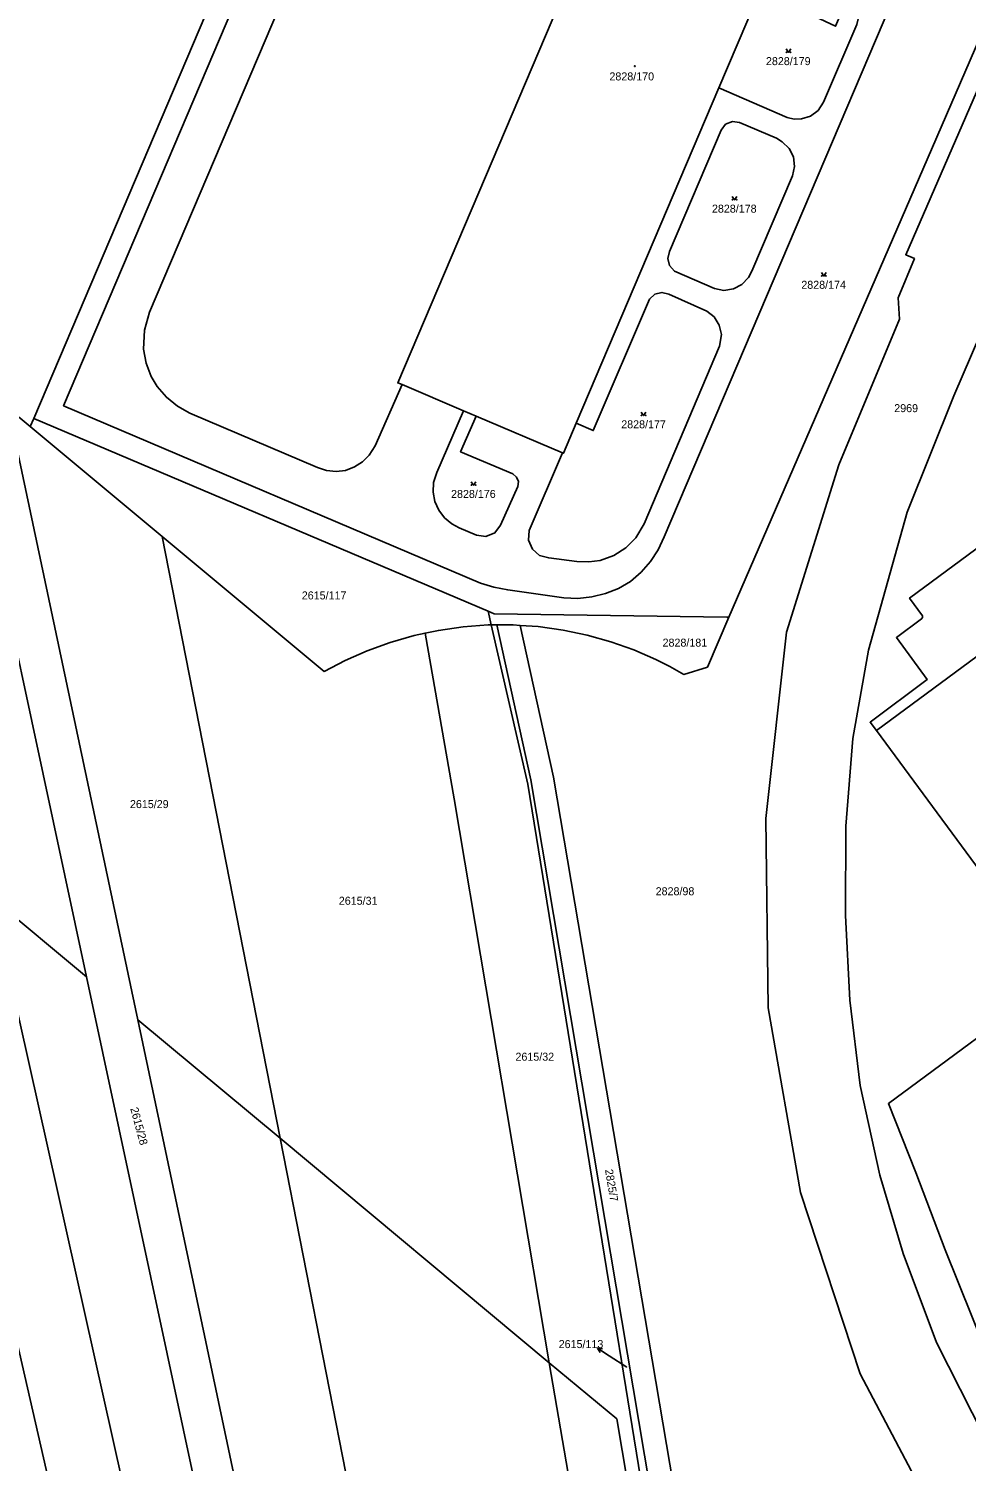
# Model space of a CAD drawing. Extents: x -596024 to -594475, y -1163820 to -1161957.
# Drawn here: x -595048.9 to -594849.7, y -1162870.2 to -1162565.8 of the extents above; entities that cross this region are included whole.
import ezdxf

# ---------------------------------------------------------------- set-up
doc = ezdxf.new("R2010")
doc.units = 0
for name, color, linetype in [('Level 1', 7, 'Continuous'), ('Level 4', 7, 'Continuous'), ('Level 5', 7, 'Continuous'), ('Level 57', 7, 'Continuous'), ('Level 60', 7, 'Continuous')]:
    doc.layers.add(name, color=color, linetype=linetype)

msp = doc.modelspace()

# ---------------------------------------------------------------- linework, layer by layer
at = {"layer": 'Level 1'}
for points in [[(-594848.96, -1162542.18), (-594851.99, -1162542.41), (-594854.86, -1162543.36), (-594857.46, -1162544.9), (-594859.6, -1162547.02), (-594861.11, -1162549.64), (-594913.9, -1162673.81), (-594915.2, -1162676.52), (-594916.84, -1162679.01), (-594918.78, -1162681.28), (-594921.04, -1162683.24), (-594923.61, -1162684.75), (-594926.38, -1162685.85), (-594929.28, -1162686.54), (-594932.25, -1162686.85), (-594935.26, -1162686.74), (-594947.14, -1162685.06), (-594950.08, -1162684.51), (-594952.91, -1162683.6), (-595041.5, -1162645.93), (-594995.82, -1162538.47), (-594955.82, -1162444.57)], [(-594957.28, -1162470.91), (-595023.23, -1162626.01), (-595024.33, -1162629.88), (-595024.5, -1162633.88), (-595023.95, -1162636.85), (-595022.88, -1162639.68), (-595021.58, -1162641.83), (-595019.66, -1162644.12), (-595017.3, -1162646.01), (-595014.7, -1162647.48), (-594987.54, -1162659.08), (-594985.61, -1162659.68), (-594983.61, -1162659.9), (-594981.61, -1162659.67), (-594979.66, -1162658.91), (-594978, -1162657.87), (-594976.57, -1162656.43), (-594975.27, -1162654.44), (-594969.59, -1162641.44)], [(-594969.59, -1162641.44), (-594970.49, -1162641.06), (-594909.2, -1162496.84), (-594908.33, -1162497.21)], [(-595047.84, -1162648.63), (-594999.13, -1162534.19), (-594992.61, -1162518.86)], [(-594822.04, -1162520.38), (-594862.6, -1162613.86), (-594860.74, -1162614.64), (-594864.21, -1162622.98), (-594863.9, -1162627.5), (-594876.82, -1162658.46), (-594887.95, -1162694.06), (-594892.35, -1162733.63), (-594891.85, -1162773.83), (-594884.93, -1162813.13), (-594872.3, -1162851.66), (-594853.89, -1162886.54)], [(-594902.28, -1162578.39), (-594888.34, -1162545.59)], [(-594902.28, -1162578.39), (-594887.77, -1162584.67), (-594886.29, -1162585.01), (-594884.76, -1162584.97), (-594882.81, -1162584.38), (-594881.18, -1162583.16), (-594880.06, -1162581.45), (-594873.01, -1162564.91), (-594872.66, -1162563.41), (-594872.95, -1162561.89), (-594873.75, -1162560.57), (-594875.09, -1162559.62), (-594877.51, -1162565.3), (-594887.39, -1162560.64), (-594885.98, -1162557.21), (-594887.95, -1162555.38), (-594888.69, -1162554.08), (-594889.18, -1162552.61), (-594889.28, -1162551.1), (-594889.09, -1162549.61), (-594888.75, -1162548.42), (-594887.67, -1162545.92), (-594888.34, -1162545.59)], [(-594900.15, -1162690.86), (-594858.06, -1162593.6), (-594837.7, -1162546.58)], [(-594820.79, -1162570.53), (-594852.35, -1162643.82), (-594862.28, -1162668.54), (-594870.52, -1162697.83), (-594873.81, -1162716.63), (-594875.35, -1162735.24), (-594875.39, -1162754.24), (-594874.5, -1162772.2), (-594872.29, -1162790.37), (-594868.13, -1162809.43), (-594863.17, -1162826.03), (-594856.03, -1162844.95), (-594843.44, -1162869.87), (-594838.3, -1162876.69)], [(-594932.57, -1162649.64), (-594902.28, -1162578.39)], [(-594912.78, -1162613.15), (-594913.15, -1162614.65), (-594912.76, -1162616.16), (-594911.7, -1162617.3), (-594903.22, -1162621.04), (-594901.21, -1162621.41), (-594899.21, -1162621.12), (-594897.39, -1162620.19), (-594895.98, -1162618.71), (-594895.29, -1162617.35), (-594886.67, -1162597.06), (-594886.24, -1162595.06), (-594886.43, -1162593.03), (-594887.34, -1162591.24), (-594888.82, -1162589.82), (-594890.08, -1162589.1), (-594897.89, -1162585.73), (-594899.43, -1162585.54), (-594900.86, -1162586.13), (-594901.81, -1162587.35), (-594912.78, -1162613.15)], [(-594868.84, -1162714.93), (-594870.17, -1162713.18), (-594858.08, -1162704.12), (-594864.59, -1162695.18), (-594859.22, -1162691.23), (-594859.01, -1162690.89), (-594859.07, -1162690.55), (-594861.79, -1162686.8), (-594753.98, -1162607.16), (-594752.15, -1162609.62)], [(-594935.5, -1162655.93), (-594942.58, -1162672.47), (-594942.71, -1162674.52), (-594941.9, -1162676.4), (-594940.39, -1162677.76), (-594938.43, -1162678.27), (-594932.46, -1162679.03), (-594929.93, -1162679.09), (-594927.48, -1162678.8), (-594924.63, -1162677.78), (-594922.09, -1162676.14), (-594919.94, -1162674.02), (-594918.14, -1162671.01), (-594902.13, -1162633.25), (-594901.72, -1162630.81), (-594902.23, -1162628.78), (-594903.3, -1162627.06), (-594904.87, -1162625.8), (-594912.91, -1162622.21), (-594914.4, -1162621.85), (-594915.92, -1162622.22), (-594917.06, -1162623.3), (-594928.97, -1162651.21), (-594932.57, -1162649.64)], [(-594868.84, -1162714.93), (-594742.69, -1162621.79), (-594713.66, -1162661.06), (-594839.86, -1162754.27)], [(-595064.49, -1162637.07), (-595036.64, -1162767.29)], [(-594969.59, -1162641.44), (-594956.56, -1162646.98)], [(-595053.16, -1162646.51), (-595048.56, -1162650.34)], [(-595025.72, -1162776.4), (-595053.16, -1162646.51)], [(-594956.56, -1162646.98), (-594962.21, -1162660.12), (-594962.9, -1162662.24), (-594963.01, -1162664.27), (-594962.63, -1162666.24), (-594961.8, -1162668.09), (-594960.59, -1162669.71), (-594959.05, -1162671.01), (-594957.48, -1162671.87), (-594953.79, -1162673.45), (-594951.78, -1162673.73), (-594949.87, -1162672.96), (-594948.65, -1162671.32), (-594944.98, -1162663.08), (-594944.85, -1162662.02), (-594945.28, -1162661.07), (-594946.08, -1162660.36), (-594957.14, -1162655.71), (-594953.87, -1162648.12)], [(-594956.56, -1162646.98), (-594953.87, -1162648.12)], [(-595048.56, -1162650.34), (-595047.84, -1162648.63)], [(-595048.56, -1162650.34), (-595020.55, -1162673.69)], [(-595047.84, -1162648.63), (-594951.3, -1162689.61)], [(-594953.87, -1162648.12), (-594935.5, -1162655.93)], [(-594935.5, -1162655.93), (-594935.28, -1162656.02), (-594932.57, -1162649.64)], [(-595020.55, -1162673.69), (-594986.14, -1162702.38), (-594981.66, -1162700.04), (-594976.97, -1162697.97), (-594972.09, -1162696.2), (-594967.04, -1162694.75), (-594964.69, -1162694.25)], [(-595020.55, -1162673.69), (-594995.49, -1162801.59)], [(-594951.3, -1162689.61), (-594950.04, -1162690.15), (-594900.58, -1162690.85), (-594900.15, -1162690.86)], [(-594951.3, -1162689.61), (-594950.64, -1162692.51)], [(-594964.69, -1162694.25), (-594961.88, -1162693.65), (-594956.62, -1162692.89), (-594951.3, -1162692.51), (-594950.64, -1162692.51)], [(-594950.64, -1162692.51), (-594949.48, -1162692.51)], [(-594950.64, -1162692.51), (-594942.9, -1162726.35), (-594904.01, -1162965.74), (-594906.27, -1162966.3)], [(-594949.48, -1162692.51), (-594945.97, -1162692.5), (-594944.53, -1162692.6)], [(-594895.5, -1163030.2), (-594896.34, -1162998.11), (-594942.24, -1162725.43), (-594949.48, -1162692.51)], [(-594944.53, -1162692.6), (-594940.65, -1162692.86), (-594935.4, -1162693.58), (-594930.25, -1162694.66), (-594925.22, -1162696.07), (-594920.36, -1162697.8), (-594915.69, -1162699.83), (-594912.69, -1162701.36), (-594909.75, -1162703.02), (-594904.74, -1162701.46), (-594900.15, -1162690.86)], [(-594911.92, -1162875.41), (-594937.42, -1162724.86), (-594944.53, -1162692.6)], [(-594964.69, -1162694.25), (-594958.51, -1162729.47), (-594938.33, -1162849.26)], [(-594839.86, -1162754.27), (-594868.84, -1162714.93)], [(-595076.87, -1162733.76), (-595010.01, -1163025.93)], [(-594995.58, -1163024.52), (-595056.72, -1162750.56)], [(-595056.72, -1162750.56), (-595036.64, -1162767.29)], [(-595036.64, -1162767.29), (-594981.78, -1163023.84)], [(-594830.23, -1162767.57), (-594866.26, -1162794.21), (-594860.48, -1162808.87), (-594854.22, -1162825.29), (-594845.65, -1162846.63), (-594845.2, -1162847.51), (-594844.22, -1162848.89), (-594830.45, -1162867.58), (-594816.13, -1162857.08)], [(-594973.5, -1163023.6), (-595025.72, -1162776.4)], [(-594995.49, -1162801.59), (-595025.72, -1162776.4)], [(-594995.49, -1162801.59), (-594951.53, -1163025.94)], [(-594938.33, -1162849.26), (-594995.49, -1162801.59)], [(-594938.33, -1162849.26), (-594917.9, -1162968.52)], [(-594938.33, -1162849.26), (-594924, -1162861.2), (-594906.27, -1162966.3)]]:
    msp.add_lwpolyline(points, dxfattribs=at)
at = {"layer": 'Level 5'}
for points in [[(-594888, -1162570.1), (-594887.5, -1162570.85), (-594887, -1162570.1)], [(-594899.45, -1162601.45), (-594898.95, -1162602.2), (-594898.45, -1162601.45)], [(-594880.49, -1162617.63), (-594879.99, -1162618.38), (-594879.49, -1162617.63)], [(-594918.78, -1162647.27), (-594918.28, -1162648.02), (-594917.78, -1162647.27)], [(-594954.89, -1162662.07), (-594954.39, -1162662.82), (-594953.89, -1162662.07)]]:
    msp.add_lwpolyline(points, dxfattribs=at)
for centre, radius in [((-594887.95, -1162570.8), 0.05), ((-594887.05, -1162570.8), 0.05), ((-594920.14, -1162573.76), 0.09), ((-594920.14, -1162573.76), 0.0521), ((-594899.4, -1162602.15), 0.05), ((-594898.5, -1162602.15), 0.05), ((-594880.44, -1162618.33), 0.05), ((-594879.54, -1162618.33), 0.05), ((-594918.73, -1162647.97), 0.05), ((-594917.83, -1162647.97), 0.05), ((-594954.84, -1162662.77), 0.05), ((-594953.94, -1162662.77), 0.05)]:
    msp.add_circle(centre, radius, dxfattribs=at)
at = {"layer": 'Level 57'}
for p, q in [((-594925.58, -1162847.81), (-594928.09, -1162846.16)), ((-594921.86, -1162850.25), (-594925.58, -1162847.81))]:
    msp.add_line(p, q, dxfattribs=at)
msp.add_lwpolyline([(-594927.53, -1162847.13), (-594928.09, -1162846.16), (-594926.98, -1162846.29)], dxfattribs=at)
at = {"layer": 'Level 60'}
for points in [[(-595059.52, -1162377.94), (-594996.96, -1162405.12), (-595003.2, -1162423.54), (-595011.25, -1162446.58), (-595019.37, -1162469.64), (-595021.91, -1162477.59), (-595014.66, -1162477.2), (-595009.74, -1162476.96), (-595003.68, -1162483.88), (-594998.47, -1162495.55), (-594992.61, -1162518.86), (-594999.13, -1162534.19), (-595047.84, -1162648.63), (-595048.56, -1162650.34), (-595053.16, -1162646.51)], [(-594853.89, -1162886.54), (-594872.3, -1162851.66), (-594884.93, -1162813.13), (-594891.85, -1162773.83), (-594892.35, -1162733.63), (-594887.95, -1162694.06), (-594876.82, -1162658.46), (-594863.9, -1162627.5), (-594864.21, -1162622.98), (-594860.74, -1162614.64), (-594862.6, -1162613.86), (-594822.04, -1162520.38), (-594817.99, -1162511.04), (-594816.51, -1162511.6), (-594796.75, -1162466.29), (-594771.27, -1162407.45), (-594764.73, -1162395.02)], [(-594837.7, -1162546.58), (-594858.06, -1162593.6), (-594900.15, -1162690.86), (-594900.58, -1162690.85), (-594950.04, -1162690.15), (-594951.3, -1162689.61), (-595047.84, -1162648.63), (-594999.13, -1162534.19), (-594992.61, -1162518.86), (-594952.46, -1162424.45), (-594811.37, -1162485.74)], [(-594848.96, -1162542.18), (-594851.99, -1162542.41), (-594854.86, -1162543.36), (-594857.46, -1162544.9), (-594859.6, -1162547.02), (-594861.11, -1162549.64), (-594913.9, -1162673.81), (-594915.2, -1162676.52), (-594916.84, -1162679.01), (-594918.78, -1162681.28), (-594921.04, -1162683.24), (-594923.61, -1162684.75), (-594926.38, -1162685.85), (-594929.28, -1162686.54), (-594932.25, -1162686.85), (-594935.26, -1162686.74), (-594947.14, -1162685.06), (-594950.08, -1162684.51), (-594952.91, -1162683.6), (-595041.5, -1162645.93), (-594995.82, -1162538.47), (-594955.82, -1162444.57), (-594889.14, -1162472.85), (-594848.66, -1162490.1)], [(-594957.28, -1162470.91), (-595023.23, -1162626.01), (-595024.33, -1162629.88), (-595024.5, -1162633.88), (-595023.95, -1162636.85), (-595022.88, -1162639.68), (-595021.58, -1162641.83), (-595019.66, -1162644.12), (-595017.3, -1162646.01), (-595014.7, -1162647.48), (-594987.54, -1162659.08), (-594985.61, -1162659.68), (-594983.61, -1162659.9), (-594981.61, -1162659.67), (-594979.66, -1162658.91), (-594978, -1162657.87), (-594976.57, -1162656.43), (-594975.27, -1162654.44), (-594969.59, -1162641.44)], [(-594909.2, -1162496.84), (-594970.49, -1162641.06), (-594969.59, -1162641.44), (-594975.27, -1162654.44), (-594976.57, -1162656.43), (-594978, -1162657.87), (-594979.66, -1162658.91), (-594981.61, -1162659.67), (-594983.61, -1162659.9), (-594985.61, -1162659.68), (-594987.54, -1162659.08), (-595014.7, -1162647.48), (-595017.3, -1162646.01), (-595019.66, -1162644.12), (-595021.58, -1162641.83), (-595022.88, -1162639.68), (-595023.95, -1162636.85), (-595024.5, -1162633.88), (-595024.33, -1162629.88), (-595023.23, -1162626.01), (-594957.28, -1162470.91)], [(-594822.04, -1162520.38), (-594862.6, -1162613.86), (-594860.74, -1162614.64), (-594864.21, -1162622.98), (-594863.9, -1162627.5), (-594876.82, -1162658.46), (-594887.95, -1162694.06), (-594892.35, -1162733.63), (-594891.85, -1162773.83), (-594884.93, -1162813.13), (-594872.3, -1162851.66), (-594853.89, -1162886.54)], [(-594995.82, -1162538.47), (-595041.5, -1162645.93), (-594952.91, -1162683.6), (-594950.08, -1162684.51), (-594947.14, -1162685.06), (-594935.26, -1162686.74), (-594932.25, -1162686.85), (-594929.28, -1162686.54), (-594926.38, -1162685.85), (-594923.61, -1162684.75), (-594921.04, -1162683.24), (-594918.78, -1162681.28), (-594916.84, -1162679.01), (-594915.2, -1162676.52), (-594913.9, -1162673.81), (-594861.11, -1162549.64)], [(-594911.92, -1162875.41), (-594937.42, -1162724.86), (-594944.53, -1162692.6), (-594940.65, -1162692.86), (-594935.4, -1162693.58), (-594930.25, -1162694.66), (-594925.22, -1162696.07), (-594920.36, -1162697.8), (-594915.69, -1162699.83), (-594912.69, -1162701.36), (-594909.75, -1162703.02), (-594904.74, -1162701.46), (-594900.15, -1162690.86), (-594858.06, -1162593.6), (-594837.7, -1162546.58)], [(-594969.59, -1162641.44), (-594956.56, -1162646.98), (-594962.21, -1162660.12), (-594962.9, -1162662.24), (-594963.01, -1162664.27), (-594962.63, -1162666.24), (-594961.8, -1162668.09), (-594960.59, -1162669.71), (-594959.05, -1162671.01), (-594957.48, -1162671.87), (-594953.79, -1162673.45), (-594951.78, -1162673.73), (-594949.87, -1162672.96), (-594948.65, -1162671.32), (-594944.98, -1162663.08), (-594944.85, -1162662.02), (-594945.28, -1162661.07), (-594946.08, -1162660.36), (-594957.14, -1162655.71), (-594953.87, -1162648.12), (-594935.5, -1162655.93), (-594942.58, -1162672.47), (-594942.71, -1162674.52), (-594941.9, -1162676.4), (-594940.39, -1162677.76), (-594938.43, -1162678.27), (-594932.46, -1162679.03), (-594929.93, -1162679.09), (-594927.48, -1162678.8), (-594924.63, -1162677.78), (-594922.09, -1162676.14), (-594919.94, -1162674.02), (-594918.14, -1162671.01), (-594902.13, -1162633.25), (-594901.72, -1162630.81), (-594902.23, -1162628.78), (-594903.3, -1162627.06), (-594904.87, -1162625.8), (-594912.91, -1162622.21), (-594914.4, -1162621.85), (-594915.92, -1162622.22), (-594917.06, -1162623.3), (-594928.97, -1162651.21), (-594932.57, -1162649.64), (-594902.28, -1162578.39), (-594887.77, -1162584.67), (-594886.29, -1162585.01), (-594884.76, -1162584.97), (-594882.81, -1162584.38), (-594881.18, -1162583.16), (-594880.06, -1162581.45), (-594873.01, -1162564.91)], [(-594843.44, -1162869.87), (-594856.03, -1162844.95), (-594863.17, -1162826.03), (-594868.13, -1162809.43), (-594872.29, -1162790.37), (-594874.5, -1162772.2), (-594875.39, -1162754.24), (-594875.35, -1162735.24), (-594873.81, -1162716.63), (-594870.52, -1162697.83), (-594862.28, -1162668.54), (-594852.35, -1162643.82), (-594820.79, -1162570.53)], [(-594820.79, -1162570.53), (-594852.35, -1162643.82), (-594862.28, -1162668.54), (-594870.52, -1162697.83), (-594873.81, -1162716.63), (-594875.35, -1162735.24), (-594875.39, -1162754.24), (-594874.5, -1162772.2), (-594872.29, -1162790.37), (-594868.13, -1162809.43), (-594863.17, -1162826.03), (-594856.03, -1162844.95), (-594843.44, -1162869.87)], [(-594753.98, -1162607.16), (-594861.79, -1162686.8), (-594859.07, -1162690.55), (-594859.01, -1162690.89), (-594859.22, -1162691.23), (-594864.59, -1162695.18), (-594858.08, -1162704.12), (-594870.17, -1162713.18), (-594868.84, -1162714.93), (-594839.86, -1162754.27)], [(-594742.69, -1162621.79), (-594868.84, -1162714.93), (-594870.17, -1162713.18), (-594858.08, -1162704.12), (-594864.59, -1162695.18), (-594859.22, -1162691.23), (-594859.01, -1162690.89), (-594859.07, -1162690.55), (-594861.79, -1162686.8), (-594753.98, -1162607.16)], [(-594830.23, -1162767.57), (-594866.26, -1162794.21), (-594860.48, -1162808.87), (-594854.22, -1162825.29), (-594845.65, -1162846.63)]]:
    msp.add_lwpolyline(points, dxfattribs=at)
for points in [[(-594969.59, -1162641.44), (-594970.49, -1162641.06), (-594909.2, -1162496.84), (-594908.33, -1162497.21), (-594886.94, -1162506.33), (-594873.99, -1162511.84), (-594885.09, -1162537.94), (-594888.34, -1162545.59), (-594902.28, -1162578.39), (-594932.57, -1162649.64), (-594935.28, -1162656.02), (-594935.5, -1162655.93), (-594953.87, -1162648.12), (-594956.56, -1162646.98)], [(-594902.28, -1162578.39), (-594888.34, -1162545.59), (-594887.67, -1162545.92), (-594888.75, -1162548.42), (-594889.09, -1162549.61), (-594889.28, -1162551.1), (-594889.18, -1162552.61), (-594888.69, -1162554.08), (-594887.95, -1162555.38), (-594885.98, -1162557.21), (-594887.39, -1162560.64), (-594877.51, -1162565.3), (-594875.09, -1162559.62), (-594873.75, -1162560.57), (-594872.95, -1162561.89), (-594872.66, -1162563.41), (-594873.01, -1162564.91), (-594880.06, -1162581.45), (-594881.18, -1162583.16), (-594882.81, -1162584.38), (-594884.76, -1162584.97), (-594886.29, -1162585.01), (-594887.77, -1162584.67)], [(-594912.78, -1162613.15), (-594913.15, -1162614.65), (-594912.76, -1162616.16), (-594911.7, -1162617.3), (-594903.22, -1162621.04), (-594901.21, -1162621.41), (-594899.21, -1162621.12), (-594897.39, -1162620.19), (-594895.98, -1162618.71), (-594895.29, -1162617.35), (-594886.67, -1162597.06), (-594886.24, -1162595.06), (-594886.43, -1162593.03), (-594887.34, -1162591.24), (-594888.82, -1162589.82), (-594890.08, -1162589.1), (-594897.89, -1162585.73), (-594899.43, -1162585.54), (-594900.86, -1162586.13), (-594901.81, -1162587.35)], [(-594913.15, -1162614.65), (-594912.78, -1162613.15), (-594901.81, -1162587.35), (-594900.86, -1162586.13), (-594899.43, -1162585.54), (-594897.89, -1162585.73), (-594890.08, -1162589.1), (-594888.82, -1162589.82), (-594887.34, -1162591.24), (-594886.43, -1162593.03), (-594886.24, -1162595.06), (-594886.67, -1162597.06), (-594895.29, -1162617.35), (-594895.98, -1162618.71), (-594897.39, -1162620.19), (-594899.21, -1162621.12), (-594901.21, -1162621.41), (-594903.22, -1162621.04), (-594911.7, -1162617.3), (-594912.76, -1162616.16)], [(-595086.06, -1162619.08), (-595064.49, -1162637.07), (-595036.64, -1162767.29), (-595056.72, -1162750.56)], [(-594935.5, -1162655.93), (-594935.28, -1162656.02), (-594932.57, -1162649.64), (-594928.97, -1162651.21), (-594917.06, -1162623.3), (-594915.92, -1162622.22), (-594914.4, -1162621.85), (-594912.91, -1162622.21), (-594904.87, -1162625.8), (-594903.3, -1162627.06), (-594902.23, -1162628.78), (-594901.72, -1162630.81), (-594902.13, -1162633.25), (-594918.14, -1162671.01), (-594919.94, -1162674.02), (-594922.09, -1162676.14), (-594924.63, -1162677.78), (-594927.48, -1162678.8), (-594929.93, -1162679.09), (-594932.46, -1162679.03), (-594938.43, -1162678.27), (-594940.39, -1162677.76), (-594941.9, -1162676.4), (-594942.71, -1162674.52), (-594942.58, -1162672.47)], [(-594868.84, -1162714.93), (-594742.69, -1162621.79), (-594713.66, -1162661.06), (-594839.86, -1162754.27)], [(-594973.5, -1163023.6), (-594981.78, -1163023.84), (-595036.64, -1162767.29), (-595064.49, -1162637.07), (-595053.16, -1162646.51), (-595025.72, -1162776.4)], [(-595053.16, -1162646.51), (-595048.56, -1162650.34), (-595020.55, -1162673.69), (-594995.49, -1162801.59), (-595025.72, -1162776.4)], [(-594956.56, -1162646.98), (-594953.87, -1162648.12), (-594957.14, -1162655.71), (-594946.08, -1162660.36), (-594945.28, -1162661.07), (-594944.85, -1162662.02), (-594944.98, -1162663.08), (-594948.65, -1162671.32), (-594949.87, -1162672.96), (-594951.78, -1162673.73), (-594953.79, -1162673.45), (-594957.48, -1162671.87), (-594959.05, -1162671.01), (-594960.59, -1162669.71), (-594961.8, -1162668.09), (-594962.63, -1162666.24), (-594963.01, -1162664.27), (-594962.9, -1162662.24), (-594962.21, -1162660.12)], [(-595020.55, -1162673.69), (-595048.56, -1162650.34), (-595047.84, -1162648.63), (-594951.3, -1162689.61), (-594950.64, -1162692.51), (-594951.3, -1162692.51), (-594956.62, -1162692.89), (-594961.88, -1162693.65), (-594964.69, -1162694.25), (-594967.04, -1162694.75), (-594972.09, -1162696.2), (-594976.97, -1162697.97), (-594981.66, -1162700.04), (-594986.14, -1162702.38)], [(-595020.55, -1162673.69), (-594986.14, -1162702.38), (-594981.66, -1162700.04), (-594976.97, -1162697.97), (-594972.09, -1162696.2), (-594967.04, -1162694.75), (-594964.69, -1162694.25), (-594958.51, -1162729.47), (-594938.33, -1162849.26), (-594995.49, -1162801.59)], [(-594860.48, -1162808.87), (-594866.26, -1162794.21), (-594830.23, -1162767.57), (-594719.25, -1162685.53), (-594700.35, -1162711.11), (-594845.04, -1162817.92), (-594816.13, -1162857.08), (-594830.45, -1162867.58), (-594844.22, -1162848.89), (-594845.2, -1162847.51), (-594845.65, -1162846.63), (-594854.22, -1162825.29)], [(-594949.48, -1162692.51), (-594950.64, -1162692.51), (-594951.3, -1162689.61), (-594950.04, -1162690.15), (-594900.58, -1162690.85), (-594900.15, -1162690.86), (-594904.74, -1162701.46), (-594909.75, -1162703.02), (-594912.69, -1162701.36), (-594915.69, -1162699.83), (-594920.36, -1162697.8), (-594925.22, -1162696.07), (-594930.25, -1162694.66), (-594935.4, -1162693.58), (-594940.65, -1162692.86), (-594944.53, -1162692.6), (-594945.97, -1162692.5)], [(-594964.69, -1162694.25), (-594961.88, -1162693.65), (-594956.62, -1162692.89), (-594951.3, -1162692.51), (-594950.64, -1162692.51), (-594942.9, -1162726.35), (-594904.01, -1162965.74), (-594906.27, -1162966.3), (-594924, -1162861.2), (-594938.33, -1162849.26), (-594958.51, -1162729.47)], [(-594950.64, -1162692.51), (-594949.48, -1162692.51), (-594942.24, -1162725.43), (-594896.34, -1162998.11), (-594895.5, -1163030.2), (-594906.27, -1162966.3), (-594904.01, -1162965.74), (-594942.9, -1162726.35)], [(-594949.48, -1162692.51), (-594945.97, -1162692.5), (-594944.53, -1162692.6), (-594937.42, -1162724.86), (-594911.92, -1162875.41), (-594891.2, -1162997.68), (-594888.97, -1163048.87), (-594887.86, -1163075.46), (-594895.5, -1163030.2), (-594896.34, -1162998.11), (-594942.24, -1162725.43)], [(-595010.01, -1163025.93), (-595024.15, -1163025.67), (-595099.02, -1162715.29), (-595076.87, -1162733.76)], [(-594995.58, -1163024.52), (-595010.01, -1163025.93), (-595076.87, -1162733.76), (-595056.72, -1162750.56)], [(-594981.78, -1163023.84), (-594995.58, -1163024.52), (-595056.72, -1162750.56), (-595036.64, -1162767.29)], [(-594951.53, -1163025.94), (-594973.5, -1163023.6), (-595025.72, -1162776.4), (-594995.49, -1162801.59)], [(-594917.9, -1162968.52), (-594907.55, -1163029.44), (-594951.53, -1163025.94), (-594995.49, -1162801.59), (-594938.33, -1162849.26)], [(-594906.27, -1162966.3), (-594917.9, -1162968.52), (-594938.33, -1162849.26), (-594924, -1162861.2)]]:
    msp.add_lwpolyline(points, close=True, dxfattribs=at)

# ---------------------------------------------------------------- texts
at = {"layer": 'Level 4'}
for s, height, p in [('2828/179', 1.7, (-594892.29, -1162573.55)), ('2828/170', 1.7, (-594925.54, -1162576.8)), ('2828/178', 1.7, (-594903.76, -1162604.9)), ('2828/174', 1.7, (-594884.78, -1162621.08)), ('2828/177', 1.7, (-594923.03, -1162650.72)), ('2828/176', 1.7, (-594959.18, -1162665.52)), ('2615/117', 1.7, (-594990.89, -1162687.08)), ('2828/181', 1.7, (-594914.25, -1162697.11)), ('2615/29', 1.7, (-595027.39, -1162731.42)), ('2828/98', 1.7, (-594915.72, -1162749.94)), ('2615/31', 1.7, (-594983.02, -1162751.96)), ('2615/32', 1.7, (-594945.5, -1162785.1)), ('2615/113', 0.1, (-594921.86, -1162850.25))]:
    msp.add_text(s, height=height, dxfattribs=at).set_placement(p)
for s, rotation, p in [('2615/28', 285.07, (-595027.34, -1162795.25)), ('2825/7', 279.5542, (-594926.49, -1162808.29))]:
    msp.add_text(s, height=1.7, rotation=rotation, dxfattribs=at).set_placement(p)
at = {"layer": 'Level 57'}
for s, p in [('2969', (-594865.04, -1162647.29)), ('2615/113', (-594936.32, -1162846.16))]:
    msp.add_text(s, height=1.7, dxfattribs=at).set_placement(p)

doc.saveas('drawing.dxf')
